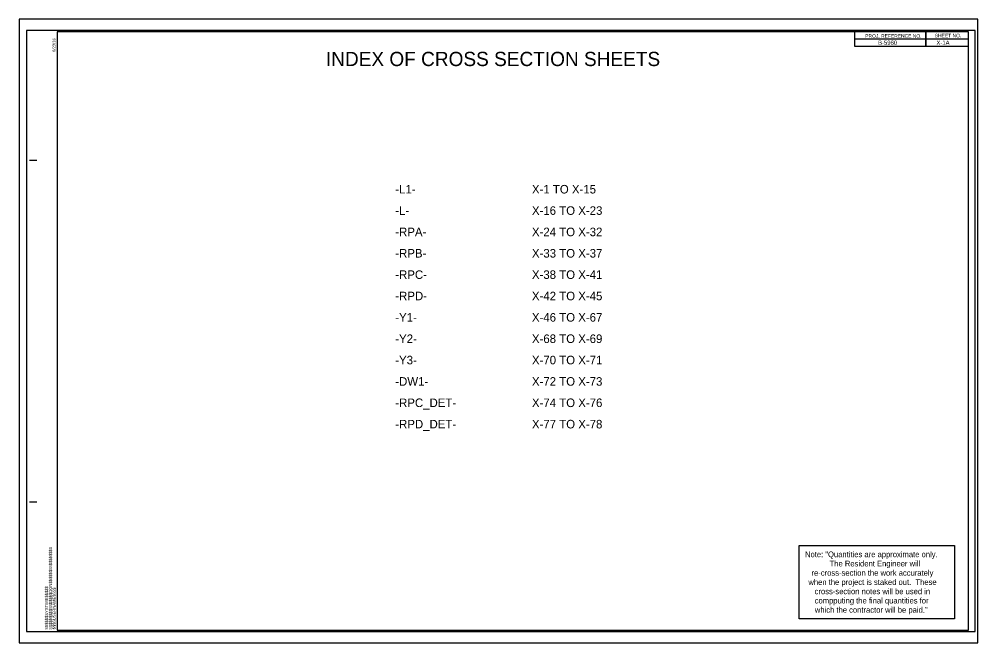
# Model space of a CAD drawing. Extents: x -13 to 323, y -5 to 215.
import ezdxf

# ---------------------------------------------------------------- set-up
doc = ezdxf.new("R2010")
doc.units = 0
for name, color, linetype in [('Default', 7, 'Continuous'), ('Prop XS Project Number', 7, 'Continuous'), ('Prop XS Sheet Number', 7, 'Continuous'), ('Sheet Cross Section CELL', 7, 'Continuous'), ('Sheet Cutting Line CELL', 7, 'Continuous'), ('Sheet Data Field CELL', 7, 'Continuous'), ('Sheet Plot Border Inside CELL', 7, 'Continuous'), ('Sheet Plot Border Outside CELL', 7, 'Continuous')]:
    doc.layers.add(name, color=color, linetype=linetype)

msp = doc.modelspace()

# ---------------------------------------------------------------- linework, layer by layer
at = {"layer": 'Default'}
msp.add_lwpolyline([(260.55, 29.73), (315.15, 29.73), (315.15, 3.92), (260.55, 3.92)], close=True, dxfattribs=at)
at = {"layer": 'Sheet Cross Section CELL'}
for p, q in [((305, 210), (305, 205)), ((305, 205), (305, 210)), ((280, 207.5), (280, 205)), ((320, 207.49), (280, 207.49)), ((280, 205), (320, 205)), ((-9.8, 165), (-7.3, 165)), ((-9.7, 165), (-7.2, 165)), ((-9.8, 45), (-7.3, 45)), ((-9.7, 45), (-7.2, 45)), ((0, 0), (0, 0)), ((0, 0), (0, 0)), ((0, 0), (0, 0)), ((0, 0), (0, 0)), ((0, 0), (0, 0)), ((0, 0), (0, 0)), ((0, 0), (0, 0))]:
    msp.add_line(p, q, dxfattribs=at)
for points in [[(320, 210), (0, 210), (0, 0), (320, 0)], [(320, 210), (280, 210), (280, 205), (320, 205)]]:
    msp.add_lwpolyline(points, close=True, dxfattribs=at)
at = {"layer": 'Sheet Cutting Line CELL'}
for p, q in [((323.3, 214.5), (-13.4, 214.5)), ((-13.4, 214.5), (-13.4, -4.5)), ((-13.4, -4.5), (323.3, -4.5))]:
    msp.add_line(p, q, dxfattribs=at)
at = {"layer": 'Sheet Plot Border Inside CELL'}
msp.add_lwpolyline([(-10.8, -0.5), (322.4, -0.5), (322.4, 210.5), (-10.8, 210.5)], close=True, dxfattribs=at)
at = {"layer": 'Sheet Plot Border Outside CELL'}
msp.add_lwpolyline([(-13.4, -4.5), (323.3, -4.5), (323.3, 214.5), (-13.4, 214.5)], close=True, dxfattribs=at)

# ---------------------------------------------------------------- texts
at = {"layer": 'Default'}
for s, p in [('Note: "Quantities are approximate only. ', (262.6, 25.57)), (' The Resident Engineer will ', (270.5, 22.32)), ('re-cross-section the work accurately ', (264.89, 19.07)), ('when the project is staked out.  These ', (263.78, 15.82)), ('cross-section notes will be used in ', (265.98, 12.57)), ('compputing the final quantities for ', (266, 9.32)), ('which the contractor will be paid."', (266.05, 6.07))]:
    msp.add_text(s, height=2, dxfattribs=at).set_placement(p)
at = {"layer": 'Prop XS Project Number'}
for s, height, p in [('B-5980', 1.5, (288.28, 205.5)), ('-L1-', 3, (118.69, 153.29)), ('X-1 TO X-15', 3, (166.69, 153.29)), ('-L-', 3, (118.69, 145.79)), ('X-16 TO X-23', 3, (166.69, 145.79)), ('-RPA- ', 3, (118.69, 138.29)), ('X-24 TO X-32', 3, (166.69, 138.29)), ('-RPB- ', 3, (118.69, 130.79)), ('X-33 TO X-37', 3, (166.69, 130.79)), ('-RPC- ', 3, (118.69, 123.29)), ('X-38 TO X-41', 3, (166.69, 123.29)), ('-RPD- ', 3, (118.69, 115.79)), ('X-42 TO X-45', 3, (166.69, 115.79)), ('-Y1- ', 3, (118.69, 108.29)), ('X-46 TO X-67', 3, (166.69, 108.29)), ('-Y2- ', 3, (118.69, 100.79)), ('X-68 TO X-69', 3, (166.69, 100.79)), ('-Y3- ', 3, (118.69, 93.29)), ('X-70 TO X-71', 3, (166.69, 93.29)), ('-DW1- ', 3, (118.69, 85.79)), ('X-72 TO X-73', 3, (166.69, 85.79)), ('-RPC_DET- ', 3, (118.69, 78.29)), ('X-74 TO X-76', 3, (166.69, 78.29)), ('-RPD_DET- ', 3, (118.69, 70.79)), ('X-77 TO X-78', 3, (166.69, 70.79))]:
    msp.add_text(s, height=height, dxfattribs=at).set_placement(p)
at = {"layer": 'Prop XS Sheet Number'}
msp.add_text('X-1A', height=1.5, dxfattribs=at).set_placement((308.77, 205.5))
at = {"layer": 'Sheet Cross Section CELL'}
for s, p in [('PROJ. REFERENCE NO.', (283.77, 207.99)), ('SHEET NO.', (308.19, 208.12))]:
    msp.add_text(s, height=1.25, dxfattribs=at).set_placement(p)
for s, p in [('6/23/16', (-0.65, 203)), ('$$$$$$$$$$$$$$$$DGN$$$$$$$$$$$$$$$$', (-1.88, 0.18)), ('$$$$$$SYSTIME$$$$$', (-3.26, 0.18)), ('$$$$USERNAME$$$$', (-0.62, 0.23))]:
    msp.add_text(s, height=1.05, rotation=90, dxfattribs=at).set_placement(p)
at = {"layer": 'Sheet Data Field CELL'}
msp.add_text('INDEX OF CROSS SECTION SHEETS', height=5, rotation=360, dxfattribs=at).set_placement((94.33, 198.03))

doc.saveas('drawing.dxf')
